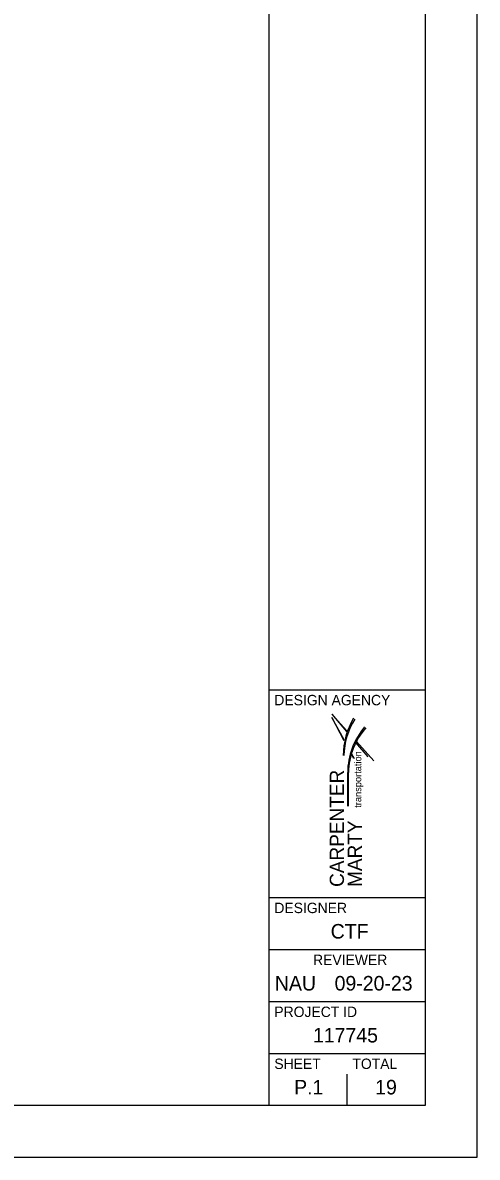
# Model space of a CAD drawing. Extents: x 0 to 34, y 0 to 22.
# Drawn here: x 29.63 to 34, y 0 to 10.92 of the extents above; entities that cross this region are included whole.
import ezdxf

# ---------------------------------------------------------------- set-up
doc = ezdxf.new("R2010")
doc.units = 0
for name, color, linetype in [('SH_Border', 7, 'Continuous'), ('SH_Cut_Line', 7, 'Continuous'), ('SH_Data', 7, 'Continuous'), ('SH_Text', 7, 'Continuous')]:
    doc.layers.add(name, color=color, linetype=linetype)

msp = doc.modelspace()

# ---------------------------------------------------------------- linework, layer by layer
at = {"layer": 'SH_Border'}
for p, q in [((32, 0.5), (32, 21.5)), ((32, 4.5), (33.5, 4.5)), ((32, 2.5), (33.5, 2.5)), ((32, 2), (33.5, 2)), ((32, 1.5), (33.5, 1.5)), ((32, 1), (33.5, 1))]:
    msp.add_line(p, q, dxfattribs=at)
msp.add_lwpolyline([(1.5, 21.5), (33.5, 21.5), (33.5, 0.5), (1.5, 0.5)], close=True, dxfattribs=at)
at = {"layer": 'SH_Cut_Line'}
msp.add_lwpolyline([(0, 0), (34, 0), (34, 22), (0, 22)], close=True, dxfattribs=at)
at = {"layer": 'SH_Data'}
for p, q in [((32.75, 3.5), (32.75, 3.5)), ((32.75, 0.5), (32.75, 0.8)), ((32.375, 0.675), (32.375, 0.675))]:
    msp.add_line(p, q, dxfattribs=at)
at = {"layer": 'SH_Text'}
for p, q in [((32.721, 4.016), (32.602, 4.232)), ((32.952, 3.853), (32.834, 3.991)), ((32.839, 4.002), (33.006, 3.816)), ((32.811, 3.84), (32.79, 3.88)), ((32.82, 3.834), (32.791, 3.886)), ((32.755, 3.378), (32.755, 3.704)), ((32.762, 3.378), (32.762, 3.704))]:
    msp.add_line(p, q, dxfattribs=at)
for points in [[(32.746, 4.104), (32.601, 4.266)], [(32.601, 4.266), (32.744, 4.098)], [(32.721, 4.016), (32.602, 4.232)], [(32.602, 4.232), (32.719, 4.011)]]:
    msp.add_lwpolyline(points, dxfattribs=at)
for centre, radius, start, end in [((33.432, 3.86), 0.721, 149.5704, 179.5529), ((33.373, 3.862), 0.654, 147.1423, 179.6525), ((33.426, 3.704), 0.671, 139.2898, 180.0106), ((33.433, 3.688), 0.672, 138.5126, 178.6075)]:
    msp.add_arc(centre, radius, start, end, dxfattribs=at)

# ---------------------------------------------------------------- texts
at = {"layer": 'SH_Data'}
for s, height, p in [('DESIGN AGENCY', 0.1, (32.05, 4.35)), ('DESIGNER', 0.1, (32.05, 2.35)), ('CTF', 0.14, (32.591, 2.105)), ('REVIEWER', 0.1, (32.422, 1.85)), ('09-20-23', 0.14, (32.629, 1.605)), ('NAU', 0.14, (32.055, 1.605)), ('PROJECT ID', 0.1, (32.05, 1.35)), ('117745', 0.14, (32.421, 1.105)), ('SHEET', 0.1, (32.05, 0.85)), ('TOTAL', 0.1, (32.8, 0.85)), ('P.1', 0.14, (32.24, 0.605)), ('19', 0.14, (33.019, 0.605))]:
    msp.add_text(s, height=height, dxfattribs=at).set_placement(p)
at = {"layer": 'SH_Text'}
for s, height, p in [('transportation', 0.06649, (32.885, 3.364)), ('CARPENTER ', 0.1367, (32.719, 2.602)), ('MARTY', 0.1367, (32.891, 2.602))]:
    msp.add_text(s, height=height, rotation=90, dxfattribs=at).set_placement(p)

doc.saveas('drawing.dxf')
